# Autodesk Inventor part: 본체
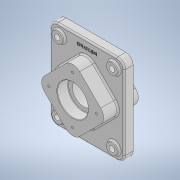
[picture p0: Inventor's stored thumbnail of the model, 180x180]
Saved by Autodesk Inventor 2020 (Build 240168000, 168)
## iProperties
Created: 2021-07
Part Number: 본체
Material: 일반
Document SubType Name: Modeling
Designer: Owner
Density: 1 g/cm^3
Appearance: 기본값
Mass: 808.432 g
Surface Area: 958.051 cm^2
Volume: 808.432 cm^3
Author: Owner
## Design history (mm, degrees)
sketch "스케치1"
  geometry: L1 (-75, 90)-(75, 90); L2 (75, 90)-(75, -90); L3 (75, -90)-(-75, -90); L4 (-75, -90)-(-75, 90); L5 (-75, 90)-(75, -90); L6 (75, 90)-(-75, -90); 1 further point
  constraints: 12 end point, 2 midpoint, 2 parallel, 1 horizontal, 1 perpendicular
  dimensions: "d0" = 150 distance of L1.start L1.end; "d1" = 180 distance of L1.end L2.end
extrude "돌출1" new body sketch "스케치1" stored distance "d2" = 18; taper "d3" = 0 deg
fillet "모깎기1" dims "d4" = 15
fillet "모깎기2" dims "d5" = 3
sketch "스케치2"
  geometry: L1 (-55, 90)-(55, 90); L2 (60, 90)-(-60, 90) reference; L3 (55, -70)-(55, 70); C1 r 11 at (55, 70); 3 further points
  constraints: 4 end point, 3 midpoint, 1 centre point, 1 coincident, 1 horizontal, 1 horizontal alignment, 1 vertical
  dimensions: "d6" = 110 distance of L1.start L1.end; "d7" = 140 distance of L3.start L3.end; "d8" = 22 diameter of C1
extrude "돌출2" join sketch "스케치2" distance "d9" = 5; taper "d10" = 0 deg
sketch "스케치3"
  geometry: C1 r 11 at (0, 0) reference; 2 further points
  constraints: 1 coincident
hole "구멍1" sketch "스케치3" at (0, 0) diameter "d11" = 11; stored, may be unused: countersink angle "d15" = 90 deg, drill point angle "d17" = 118 deg; dims "d12" = 8, "d13" = 4, "d14" = 2, "d16" = 11
sketch "스케치5"
  geometry: L1 (0, 70.711)-(-70.711, 0); L2 (-70.711, 0)-(0, -70.711); L3 (0, -70.711)-(70.711, 0); L4 (70.711, 0)-(0, 70.711); 1 further point
  constraints: 8 end point, 2 horizontal alignment, 2 parallel, 2 vertical alignment, 1 perpendicular
  dimensions: "d19" = 100 distance between parallel lines of L3 L1
extrude "돌출3" join sketch "스케치5" distance "d20" = 29; taper "d21" = 0 deg
sketch "스케치6"
  geometry: L1 (0, 70.711)-(-70.711, 0) reference; L2 (-70.711, 0)-(0, -70.711) reference; L3 (0, 70.711)-(-70.711, 0); L4 (-70.711, 0)-(0, -70.711); L5 (0, -70.711)-(70.711, 0); L6 (70.711, 0)-(0, 70.711); 2 further points
  constraints: 8 end point, 2 parallel, 2 perpendicular
extrude "돌출4" join sketch "스케치6" distance "d22" = 23; taper "d23" = 0 deg
fillet "모깎기3" dims "d24" = 20
sketch "스케치7" dims "d25" = 96
  geometry: L1 (0, 0)-(0, 48); 1 further point
  constraints: 2 end point, 1 coincident, 1 vertical, 1 vertical alignment, 2 other
hole "구멍2" sketch "스케치7" at (0, 48) diameter "d26" = 4.917; stored, may be unused: countersink angle "d30" = 90 deg, drill point angle "d32" = 118 deg; dims "d27" = 10, "d28" = 4, "d29" = 2, "d31" = 13
node "작업 평면2"
sketch "스케치8"
  geometry: L1 (56.569, 38)-(14.142, 38) reference; L2 (31, 38)-(31, 16); L3 (31, 16)-(22.5, 16); L4 (22.5, 16)-(22.5, -10); L5 (22.5, -10)-(31, -10); L6 (31, -10)-(31, -32); L7 (14.142, -32)-(56.569, -32) reference; L8 (-14.142, 38)-(14.142, 38) reference; L9 (0, 38)-(0, -32); L10 (14.142, -32)-(-14.142, -32) reference; 1 further point
  constraints: 12 end point, 4 perpendicular, 4 point on line, 2 midpoint
  dimensions: "d35" = 62 diameter of L2 L9; "d36" = 45 diameter of L4 L9; "d37" = 22 distance of L2.start L2.end; "d38" = 22 distance of L5.end L6.end
revolve "회전1" sketch "스케치8" stored, may be unused: angle "d39" = 90 deg
fillet "모깎기4" dims "d40" = 1
chamfer "모따기1" distance "d41" = 1; stored, may be unused: second distance "d42" = 2, angle "d43" = 45 deg
chamfer "모따기2" distance "d44" = 1; stored, may be unused: second distance "d45" = 2, angle "d46" = 45 deg
fillet "모깎기5" dims "d47" = 3
sketch "스케치9"
  geometry: L1 (-75, -75)-(-75, 75) reference; A1 r 20 centre (0, 42.426) between (14.142, 56.569) and (-14.142, 56.569) reference; 3 further points
  constraints: 1 horizontal alignment, 1 point on circle, 1 vertical alignment, 1 other
feature "엠보싱1" sketch "스케치9" dims "d0" = 150, "d1" = 180, "d55" = 0.5, "d56" = 0
fillet "모깎기6" dims "d57" = 3
fillet "모깎기7" dims "d58" = 3
sketch "스케치10"
  geometry: L1 (0, 0)-(0, 48); C1 r 48 at (0, 0); C2 r 22.5 at (0, 0) reference; C3 r 2.458 at (0, 48) reference; 1 further point
  constraints: 2 end point, 1 centre point, 1 coincident, 1 vertical
  dimensions: "d59" = 96 diameter of C1
hole "구멍3" sketch "스케치10" at (0, 48) diameter "d60" = 4.917; stored, may be unused: countersink angle "d64" = 90 deg, drill point angle "d66" = 118 deg; dims "d61" = 10, "d62" = 4, "d63" = 2, "d65" = 13
node "솔리드1"
mirror "미러1"
mirror "미러2"
mirror "미러3"
mirror "미러4"
pattern_circular "원형 패턴1" dims angle "d49" = 360 deg
pattern_circular "원형 패턴3" dims angle "d68" = 360 deg
node "작업 평면1"
feature "A9D066F2-1C7D-4E18-AEED-F7BC21143FA4" dims "d11" = 11, "d12" = 8, "d13" = 4, "d14" = 2, "d15" = 90 deg, "d16" = 11, "d17" = 118 deg
other parameters: "d33" = 0
